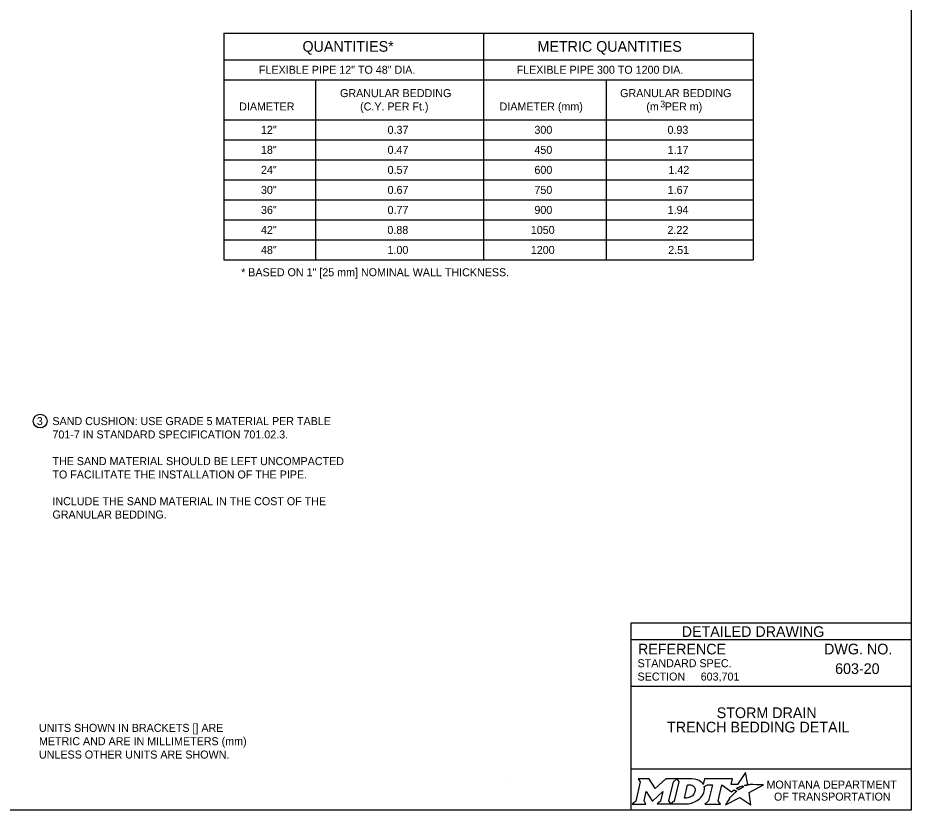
# Model space of a CAD drawing. Extents: x 49991.4 to 50061.4, y 49960.6 to 50011.4.
# Drawn here: x 50010.06 to 50016.75, y 49987.8 to 49993.73 of the extents above; entities that cross this region are included whole.
import ezdxf

# ---------------------------------------------------------------- set-up
doc = ezdxf.new("R2010")
doc.units = 0
for name, color, linetype in [('Default', 7, 'Continuous'), ('Level 1', 7, 'Continuous'), ('Level 2', 7, 'Continuous'), ('Level 25', 7, 'Continuous'), ('Level 5', 7, 'Continuous')]:
    doc.layers.add(name, color=color, linetype=linetype)

msp = doc.modelspace()

# ---------------------------------------------------------------- linework, layer by layer
at = {"layer": 'Default'}
for points in [[(50014.7056, 49988.0338), (50014.7197, 49988.0104), (50014.6862, 49987.8671), (50014.6605, 49987.8446), (50014.7621, 49987.8446), (50014.7486, 49987.8674), (50014.7648, 49987.9375), (50014.8085, 49987.8685), (50014.8138, 49987.8685), (50014.8889, 49987.938), (50014.8725, 49987.8669), (50014.8478, 49987.8449), (50014.9494, 49987.8449), (50014.9356, 49987.8682), (50014.9688, 49988.0106)], [(50014.9688, 49988.0106), (50014.9941, 49988.0338), (50014.9117, 49988.0338), (50014.8321, 49987.9608), (50014.7876, 49988.0335), (50014.7056, 49988.0338)], [(50015.1077, 49988.0338), (50014.9941, 49988.0338), (50015.0088, 49988.0109), (50014.9749, 49987.8671), (50014.9494, 49987.8449), (50015.06, 49987.8449)], [(50015.5126, 49987.9811), (50015.5023, 49987.9867), (50015.5139, 49987.9895), (50015.5255, 49987.9915), (50015.5081, 49988.0816), (50015.4486, 49987.9903), (50015.4013, 49987.9896), (50015.4116, 49988.0337), (50015.2024, 49988.0338), (50015.1923, 49987.9913), (50015.1865, 49987.9996)], [(50015.1317, 49987.9471), (50015.1305, 49987.939), (50015.1273, 49987.9297), (50015.1231, 49987.9215), (50015.1175, 49987.914), (50015.111, 49987.9071), (50015.1031, 49987.9008), (50015.0948, 49987.8961), (50015.0857, 49987.8922), (50015.0766, 49987.8899), (50015.0674, 49987.889), (50015.0515, 49987.889), (50015.0751, 49987.989), (50015.0911, 49987.989), (50015.0987, 49987.9884), (50015.1063, 49987.9865), (50015.1129, 49987.9835), (50015.119, 49987.9793), (50015.1238, 49987.9743), (50015.1275, 49987.9683), (50015.1302, 49987.9621), (50015.1318, 49987.9547), (50015.1318, 49987.9517), (50015.1317, 49987.9471)], [(50015.1991, 49987.9747), (50015.2237, 49987.9878), (50015.2606, 49987.9878), (50015.232, 49987.8673), (50015.2045, 49987.8446), (50015.3207, 49987.8446), (50015.3037, 49987.8675), (50015.3319, 49987.9877), (50015.4032, 49987.936), (50015.4243, 49987.9511), (50015.444, 49987.9402)], [(50015.3882, 49987.8843), (50015.3729, 49987.8599), (50015.3682, 49987.8524), (50015.3624, 49987.8438), (50015.3601, 49987.8395), (50015.4654, 49987.8926), (50015.5493, 49987.8375), (50015.5362, 49987.9302), (50015.6431, 49987.9886), (50015.5938, 49987.9894), (50015.5637, 49987.9898), (50015.5429, 49987.9901), (50015.5361, 49987.9886), (50015.5312, 49987.9874), (50015.5228, 49987.9851), (50015.5126, 49987.9811)], [(50015.4622, 49987.9535), (50015.4598, 49987.9518), (50015.4415, 49987.9614), (50015.4518, 49987.9671), (50015.4559, 49987.9693), (50015.4645, 49987.9733), (50015.4702, 49987.9759), (50015.4781, 49987.9789), (50015.4854, 49987.9816), (50015.4972, 49987.9742), (50015.4932, 49987.9721), (50015.4886, 49987.9696), (50015.4844, 49987.9674), (50015.4794, 49987.9645), (50015.4775, 49987.9634), (50015.4748, 49987.9618), (50015.4723, 49987.9604), (50015.47, 49987.9588), (50015.4674, 49987.957), (50015.4647, 49987.9552), (50015.4622, 49987.9535)], [(50015.4021, 49987.9004), (50015.4021, 49987.9004)], [(50015.1057, 49987.8522), (50015.1141, 49987.8548), (50015.1271, 49987.8602), (50015.1475, 49987.8712)]]:
    msp.add_lwpolyline(points, dxfattribs=at)
for centre, radius, start, end in [((50015.1308, 49987.9554), 0.0709, 339.53292, 15.85821), ((50015.0868, 49987.9727), 0.1183, 300.91025, 339.13831)]:
    msp.add_arc(centre, radius, start, end, dxfattribs=at)
for centre, major_axis, ratio, start_param, end_param in [((50015.1056, 49987.9864), (0.0834, -0.0037), 0.568097, 0.61298, 1.570796), ((50015.1612, 49987.9937), (0.0361, -0.0295), 0.469099, 1.225588, 1.570796), ((50015.3952, 49987.8923), (-0.00694, -0.00806), 0.008222, 0, 3.137361), ((50015.4119, 49987.9106), (-0.0098, -0.0102), 0.016458, 3.141593, 6.279097), ((50015.4329, 49987.9305), (-0.0112, -0.0097), 0.021651, 3.157348, 6.283185), ((50015.0603, 49987.9932), (0, 0.1484), 0.987302, 3.139398, 3.456847)]:
    msp.add_ellipse(centre, major_axis=major_axis, ratio=ratio, start_param=start_param, end_param=end_param, dxfattribs=at)
at = {"layer": 'Level 1'}
msp.add_lwpolyline([(49999.3835, 49998.9992), (50016.7501, 49998.9992), (50016.7501, 49987.7988), (49999.3835, 49987.7988)], close=True, dxfattribs=at)
at = {"layer": 'Level 2'}
for p, q in [((50011.5997, 49993.6201), (50011.5997, 49991.9201)), ((50011.5997, 49993.6201), (50015.5658, 49993.6201)), ((50013.5463, 49993.6201), (50013.5463, 49991.9201)), ((50015.5658, 49993.6201), (50015.5658, 49991.9201)), ((50011.5997, 49993.4201), (50015.5658, 49993.4201)), ((50011.5997, 49993.2701), (50015.5658, 49993.2701)), ((50012.2872, 49993.2701), (50012.2872, 49991.9201)), ((50014.465, 49993.2701), (50014.465, 49991.9201)), ((50011.9435, 49993.0931), (50011.9435, 49993.0931)), ((50011.5997, 49992.9701), (50015.5658, 49992.9701)), ((50011.5997, 49992.8201), (50015.5658, 49992.8201)), ((50011.5997, 49992.6701), (50015.5658, 49992.6701)), ((50011.5997, 49992.5201), (50015.5658, 49992.5201)), ((50011.5997, 49992.3701), (50015.5658, 49992.3701)), ((50011.5997, 49992.2201), (50015.5658, 49992.2201)), ((50011.5997, 49992.0701), (50015.5658, 49992.0701)), ((50011.5997, 49991.9201), (50015.5658, 49991.9201)), ((50013.7461, 49988.0122), (50013.7461, 49988.0122))]:
    msp.add_line(p, q, dxfattribs=at)
msp.add_circle((50010.2244, 49990.7132), 0.0517, dxfattribs=at)
at = {"layer": 'Level 5'}
for p, q in [((50016.7501, 49989.1988), (50014.6501, 49989.1988)), ((50014.6501, 49989.1988), (50014.6501, 49987.7988)), ((50016.7501, 49989.0738), (50014.6501, 49989.0738)), ((50016.3862, 49988.8587), (50016.3862, 49988.8587)), ((50015.1444, 49988.7993), (50015.1444, 49988.7993)), ((50016.7501, 49988.7238), (50014.6501, 49988.7238)), ((50015.7001, 49988.4747), (50015.7001, 49988.4747)), ((50016.7501, 49988.1057), (50014.6501, 49988.1057))]:
    msp.add_line(p, q, dxfattribs=at)

# ---------------------------------------------------------------- texts
at = {"layer": 'Default'}
for s, p in [('MONTANA DEPARTMENT', (50015.6663, 49987.96)), ('OF TRANSPORTATION', (50015.7225, 49987.87))]:
    msp.add_text(s, height=0.06, dxfattribs=at).set_placement(p)
at = {"layer": 'Level 2'}
for s, height, p in [('QUANTITIES*', 0.08, (50012.1896, 49993.4801)), ('METRIC QUANTITIES', 0.08, (50013.9505, 49993.4801)), ('FLEXIBLE PIPE 12" TO 48" DIA.', 0.06, (50011.8634, 49993.3151)), ('FLEXIBLE PIPE 300 TO 1200 DIA.', 0.06, (50013.7942, 49993.3151)), ('GRANULAR BEDDING', 0.06, (50012.4712, 49993.1401)), ('GRANULAR BEDDING', 0.06, (50014.5699, 49993.1401)), ('3', 0.05, (50014.8699, 49993.0633)), ('DIAMETER', 0.06, (50011.7152, 49993.0401)), ('(C.Y. PER Ft.)', 0.06, (50012.6214, 49993.0401)), ('DIAMETER (mm)', 0.06, (50013.6665, 49993.0401)), ('(m  PER m)', 0.06, (50014.7659, 49993.0401)), ('12"', 0.06, (50011.8786, 49992.8651)), ('0.37', 0.06, (50012.8273, 49992.8651)), ('300', 0.06, (50013.9275, 49992.8651)), ('0.93', 0.06, (50014.9245, 49992.8651)), ('18"', 0.06, (50011.8786, 49992.7151)), ('0.47', 0.06, (50012.8273, 49992.7151)), ('450', 0.06, (50013.9275, 49992.7151)), ('1.17', 0.06, (50014.9259, 49992.7151)), ('24"', 0.06, (50011.8786, 49992.5651)), ('0.57', 0.06, (50012.8273, 49992.5651)), ('600', 0.06, (50013.9275, 49992.5651)), ('1.42', 0.06, (50014.9313, 49992.5651)), ('30"', 0.06, (50011.8786, 49992.4151)), ('0.67', 0.06, (50012.8273, 49992.4151)), ('750', 0.06, (50013.9275, 49992.4151)), ('1.67', 0.06, (50014.9259, 49992.4151)), ('36"', 0.06, (50011.8786, 49992.2651)), ('0.77', 0.06, (50012.8273, 49992.2651)), ('900', 0.06, (50013.9275, 49992.2651)), ('1.94', 0.06, (50014.9257, 49992.2651)), ('42"', 0.06, (50011.8786, 49992.1151)), ('0.88', 0.06, (50012.8261, 49992.1151)), ('1050', 0.06, (50013.9006, 49992.1151)), ('2.22', 0.06, (50014.9246, 49992.1151)), ('48"', 0.06, (50011.8786, 49991.9651)), ('1.00', 0.06, (50012.8267, 49991.9651)), ('1200', 0.06, (50013.9006, 49991.9651)), ('2.51', 0.06, (50014.93, 49991.9651)), ('* BASED ON 1" [25 mm] NOMINAL WALL THICKNESS.', 0.06, (50011.73, 49991.7981)), ('3', 0.06, (50010.1992, 49990.6832)), ('SAND CUSHION: USE GRADE 5 MATERIAL PER TABLE ', 0.06, (50010.3162, 49990.6832)), ('701-7 IN STANDARD SPECIFICATION 701.02.3. ', 0.06, (50010.3162, 49990.5832)), ('THE SAND MATERIAL SHOULD BE LEFT UNCOMPACTED ', 0.06, (50010.3162, 49990.3832)), ('TO FACILITATE THE INSTALLATION OF THE PIPE.', 0.06, (50010.3162, 49990.2832)), ('INCLUDE THE SAND MATERIAL IN THE COST OF THE', 0.06, (50010.3162, 49990.0832)), ('GRANULAR BEDDING.', 0.06, (50010.3162, 49989.9832)), ('UNITS SHOWN IN BRACKETS [] ARE ', 0.06, (50010.2153, 49988.3852)), ('METRIC AND ARE IN MILLIMETERS (mm) ', 0.06, (50010.2153, 49988.2852)), ('UNLESS OTHER UNITS ARE SHOWN.', 0.06, (50010.2153, 49988.1852))]:
    msp.add_text(s, height=height, dxfattribs=at).set_placement(p)
at = {"layer": 'Level 25'}
for s, height, p in [('603-20', 0.08, (50016.1805, 49988.8187)), ('603,701', 0.06, (50015.1733, 49988.7693)), ('STORM DRAIN', 0.08, (50015.2934, 49988.4883)), ('TRENCH BEDDING DETAIL', 0.08, (50014.9211, 49988.3811))]:
    msp.add_text(s, height=height, dxfattribs=at).set_placement(p)
at = {"layer": 'Level 5'}
for s, height, p in [('DETAILED DRAWING', 0.0799, (50015.0311, 49989.0963)), ('REFERENCE', 0.08, (50014.7037, 49988.9654)), ('DWG. NO.', 0.08, (50016.0979, 49988.9654)), ('STANDARD SPEC.', 0.06, (50014.7004, 49988.8694)), ('SECTION', 0.06, (50014.7004, 49988.7694))]:
    msp.add_text(s, height=height, dxfattribs=at).set_placement(p)

doc.saveas('drawing.dxf')
